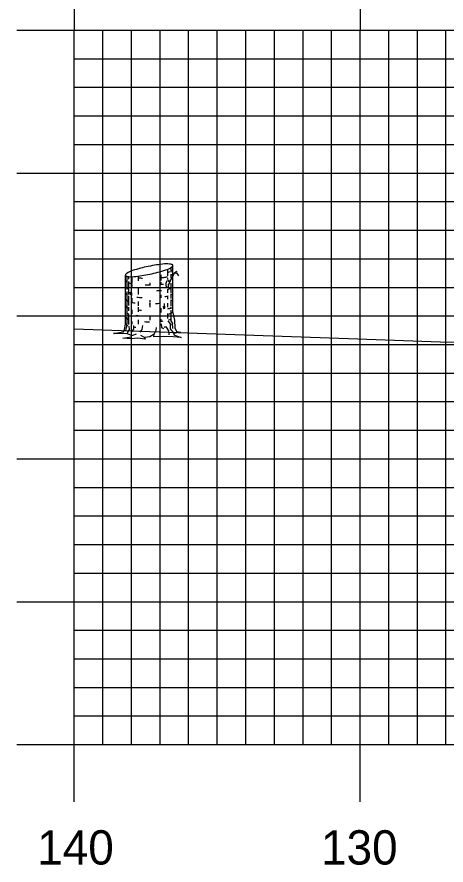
# Model space of a CAD drawing. Extents: x 1771235 to 1771579, y 442591 to 442811.
# Drawn here: x 1771259.06 to 1771274.07, y 442649.45 to 442679.13 of the extents above; entities that cross this region are included whole.
import ezdxf

# ---------------------------------------------------------------- set-up
doc = ezdxf.new("R2010")
doc.units = 0
for name, color, linetype in [('H_V ANNOTATION', 7, 'Continuous'), ('M_Trees_Conifer_Pay', 7, 'Continuous'), ('MAJOR', 7, 'Continuous'), ('MINOR', 7, 'Continuous'), ('S_Roadway_Centerline', 7, 'Continuous')]:
    doc.layers.add(name, color=color, linetype=linetype)

msp = doc.modelspace()

# ---------------------------------------------------------------- linework, layer by layer
at = {"layer": 'M_Trees_Conifer_Pay'}
for p, q in [((1771264.517, 442668.783), (1771264.517, 442670.429)), ((1771262.853, 442668.372), (1771262.853, 442670.094)), ((1771264.1, 442670.1), (1771264.1, 442669.901)), ((1771264.328, 442670.296), (1771264.328, 442670.073)), ((1771264.446, 442670.357), (1771264.446, 442670.195)), ((1771264.446, 442670.127), (1771264.446, 442669.999)), ((1771262.901, 442670.057), (1771262.901, 442669.586)), ((1771262.959, 442670.046), (1771262.959, 442669.948)), ((1771262.959, 442669.874), (1771262.959, 442669.67)), ((1771263.084, 442670.038), (1771263.084, 442669.805)), ((1771263.304, 442670.058), (1771263.304, 442669.89)), ((1771263.71, 442669.826), (1771263.71, 442669.731)), ((1771264.1, 442669.843), (1771264.1, 442669.754)), ((1771264.328, 442669.985), (1771264.328, 442669.937)), ((1771264.386, 442669.802), (1771264.334, 442669.742)), ((1771264.446, 442669.812), (1771264.446, 442669.476)), ((1771262.901, 442669.521), (1771262.901, 442669.213)), ((1771262.959, 442669.612), (1771262.959, 442669.412)), ((1771263.084, 442669.765), (1771263.084, 442669.691)), ((1771263.304, 442669.653), (1771263.304, 442669.416)), ((1771264.328, 442669.602), (1771264.328, 442669.47)), ((1771262.959, 442669.365), (1771262.959, 442669.029)), ((1771263.084, 442669.287), (1771263.084, 442669.149)), ((1771263.71, 442669.213), (1771263.71, 442669.139)), ((1771264.1, 442669.407), (1771264.1, 442669.302)), ((1771264.328, 442669.359), (1771264.328, 442669.25)), ((1771264.446, 442669.439), (1771264.446, 442669.277)), ((1771264.446, 442669.229), (1771264.446, 442669.013)), ((1771262.901, 442669.166), (1771262.901, 442668.674)), ((1771262.959, 442668.976), (1771262.959, 442668.84)), ((1771263.304, 442669.172), (1771263.304, 442669.019)), ((1771263.304, 442668.976), (1771263.304, 442668.803)), ((1771263.71, 442669.114), (1771263.71, 442668.966)), ((1771264.1, 442668.935), (1771264.1, 442668.788)), ((1771264.328, 442669.114), (1771264.328, 442668.972)), ((1771264.446, 442668.982), (1771264.446, 442668.908)), ((1771262.901, 442668.62), (1771262.901, 442668.372)), ((1771262.959, 442668.741), (1771262.959, 442668.363)), ((1771263.084, 442668.877), (1771263.084, 442668.735)), ((1771263.71, 442668.674), (1771263.71, 442668.521)), ((1771264.328, 442668.745), (1771264.328, 442668.573)), ((1771264.446, 442668.867), (1771264.446, 442668.694)), ((1771263.084, 442668.473), (1771263.084, 442668.379)), ((1771263.304, 442668.525), (1771263.304, 442668.372)), ((1771264.1, 442668.556), (1771264.1, 442668.468)), ((1771263.084, 442667.979), (1771263.247, 442668.043)), ((1771263.521, 442667.915), (1771263.395, 442667.979))]:
    msp.add_line(p, q, dxfattribs=at)
for points in [[(1771264.334, 442669.928), (1771264.371, 442669.853), (1771264.418, 442669.91), (1771264.476, 442669.979), (1771264.569, 442670.172), (1771264.633, 442670.22), (1771264.664, 442670.226)], [(1771264.349, 442669.674), (1771264.386, 442669.802), (1771264.449, 442669.917), (1771264.48, 442669.985), (1771264.549, 442670.131)], [(1771264.563, 442670.16), (1771264.639, 442670.168), (1771264.711, 442670.069)], [(1771264.301, 442669.89), (1771264.27, 442669.805), (1771264.266, 442669.738), (1771264.297, 442669.674)], [(1771263.033, 442669.4), (1771263.027, 442669.495), (1771263.07, 442669.472), (1771263.07, 442669.378)], [(1771264.172, 442669.001), (1771264.184, 442668.924), (1771264.231, 442668.935), (1771264.219, 442669.101)], [(1771264.517, 442668.783), (1771264.569, 442668.521), (1771264.585, 442668.247), (1771264.643, 442668.122), (1771264.779, 442668.091), (1771264.548, 442668.054), (1771264.548, 442668.054), (1771264.554, 442668.006), (1771264.802, 442667.912), (1771264.527, 442667.928), (1771264.172, 442667.949), (1771263.85, 442667.938), (1771263.857, 442668.021), (1771263.708, 442667.938), (1771263.521, 442667.915), (1771263.546, 442667.847), (1771263.278, 442667.891), (1771263.058, 442667.864), (1771262.765, 442667.881), (1771263.054, 442667.938), (1771263.084, 442667.979), (1771262.922, 442668.037), (1771262.685, 442668.048), (1771262.444, 442668.048), (1771262.786, 442668.105), (1771262.827, 442668.185), (1771262.853, 442668.372)], [(1771264.443, 442668.64), (1771264.449, 442668.494), (1771264.496, 442668.426), (1771264.507, 442668.227)], [(1771262.901, 442668.325), (1771262.88, 442668.247), (1771262.86, 442668.153)], [(1771262.979, 442668.305), (1771262.985, 442668.189), (1771262.932, 442668.101), (1771262.922, 442668.037)], [(1771263.142, 442668.332), (1771263.142, 442668.2), (1771263.054, 442668.101)], [(1771263.369, 442668.091), (1771263.436, 442668.185), (1771263.463, 442668.325)], [(1771264.107, 442668.389), (1771264.118, 442668.263), (1771264.192, 442668.22)], [(1771264.344, 442668.494), (1771264.418, 442668.389), (1771264.423, 442668.216), (1771264.548, 442668.054)], [(1771263.857, 442668.021), (1771263.931, 442668.162), (1771263.941, 442668.263)], [(1771264.386, 442668), (1771264.371, 442668.138), (1771264.297, 442668.267)]]:
    msp.add_lwpolyline(points, dxfattribs=at)
for centre, radius, start, end in [((1771264.709, 442665.327), 5.179, 101.7194, 108.0594), ((1771264.709, 442665.327), 5.179, 95.3794, 101.7194), ((1771264.299, 442669.685), 0.802, 79.2194, 95.3794), ((1771264.019, 442671.035), 0.802, 288.0594, 304.2194), ((1771264.402, 442670.226), 0.251, 71.0501, 79.2194), ((1771264.329, 442670.58), 0.251, 304.2194, 312.3887), ((1771264.457, 442670.386), 0.0817, 56.7194, 71.0501), ((1771264.442, 442670.455), 0.0817, 312.3887, 326.7194), ((1771264.473, 442670.41), 0.0527, 46.923, 56.7194), ((1771264.487, 442670.425), 0.0314, 34.2194, 46.923), ((1771264.467, 442670.439), 0.0527, 326.7194, 336.5158), ((1771264.491, 442670.428), 0.0264, 23.4074, 34.2194), ((1771264.486, 442670.431), 0.0314, 336.5158, 349.2194), ((1771264.495, 442670.43), 0.0226, 11.7194, 23.4074), ((1771264.495, 442670.43), 0.0226, 0.0315, 11.7194), ((1771264.491, 442670.43), 0.0264, 349.2194, 0.0315), ((1771262.885, 442670.093), 0.0314, 156.5158, 169.2194), ((1771262.88, 442670.094), 0.0264, 169.2194, 180.0315), ((1771262.876, 442670.094), 0.0226, 180.0315, 191.7194), ((1771262.876, 442670.094), 0.0226, 191.7194, 203.4074), ((1771262.88, 442670.095), 0.0264, 203.4074, 214.2194), ((1771262.904, 442670.084), 0.0527, 146.7194, 156.5158), ((1771262.884, 442670.098), 0.0314, 214.2194, 226.923), ((1771262.929, 442670.069), 0.0817, 132.3887, 146.7194), ((1771262.898, 442670.114), 0.0527, 226.923, 236.7194), ((1771262.914, 442670.138), 0.0817, 236.7194, 251.0501), ((1771263.042, 442669.944), 0.251, 124.2194, 132.3887), ((1771263.352, 442669.488), 0.802, 108.0594, 124.2194), ((1771262.662, 442675.197), 5.179, 275.3794, 281.7194), ((1771262.662, 442675.197), 5.179, 281.7194, 288.0594), ((1771264.187, 442670.743), 0.571, 284.4317, 292.4132), ((1771264.187, 442670.589), 0.571, 297.0237, 300), ((1771264.386, 442670.398), 0.172, 300, 311.2506), ((1771264.386, 442670.244), 0.172, 300, 311.2506), ((1771264.458, 442670.315), 0.0624, 311.2506, 330), ((1771264.458, 442670.161), 0.0624, 311.2506, 330), ((1771264.474, 442670.306), 0.0441, 330, 343.9485), ((1771264.474, 442670.152), 0.0441, 330, 343.9485), ((1771264.484, 442670.303), 0.0334, 343.9485, 354.2151), ((1771264.484, 442670.149), 0.0334, 343.9485, 354.2151), ((1771262.886, 442669.916), 0.0334, 163.9485, 180), ((1771262.886, 442669.916), 0.0334, 180, 196.0515), ((1771262.896, 442669.919), 0.0441, 196.0515, 210), ((1771262.912, 442669.928), 0.0624, 210, 228.7494), ((1771262.984, 442670.011), 0.172, 228.7494, 240), ((1771262.969, 442670.298), 0.251, 251.0501, 259.2194), ((1771263.183, 442670.356), 0.571, 240, 240.3367), ((1771263.072, 442670.839), 0.802, 259.2194, 275.3794), ((1771263.183, 442670.356), 0.571, 246.8597, 257.9846), ((1771263.686, 442674.106), 4.124, 264.6955, 266.7331), ((1771263.684, 442673.873), 4.124, 275.7849, 277.0558), ((1771263.686, 442674.106), 4.124, 276.238, 278.1032), ((1771264.187, 442670.589), 0.571, 278.1032, 284.3667), ((1771262.886, 442669.469), 0.0334, 163.9485, 180), ((1771263.185, 442670.145), 0.571, 240, 247.0587), ((1771263.684, 442673.873), 4.124, 268.0751, 270), ((1771263.684, 442673.873), 4.124, 270, 270.3581), ((1771263.686, 442673.662), 4.124, 273.7052, 275.9504), ((1771264.186, 442670.145), 0.571, 284.4493, 297.0429), ((1771264.484, 442669.705), 0.0334, 343.9485, 354.2151), ((1771262.886, 442669.469), 0.0334, 180, 196.0515), ((1771262.886, 442669.259), 0.0334, 163.9485, 180), ((1771262.886, 442669.259), 0.0334, 180, 196.0515), ((1771262.896, 442669.472), 0.0441, 196.0515, 210), ((1771262.896, 442669.262), 0.0441, 196.0515, 210), ((1771262.912, 442669.481), 0.0624, 210, 228.7494), ((1771262.912, 442669.271), 0.0624, 210, 228.7494), ((1771262.984, 442669.564), 0.172, 228.7494, 240), ((1771262.984, 442669.354), 0.172, 228.7494, 240), ((1771263.183, 442669.909), 0.571, 240, 240.3367), ((1771263.183, 442669.699), 0.571, 240, 246.8597), ((1771263.684, 442673.426), 4.124, 264.081, 266.6676), ((1771263.684, 442673.426), 4.124, 277.6125, 278.1032), ((1771264.185, 442669.909), 0.571, 278.1032, 286.9296), ((1771264.185, 442669.909), 0.571, 297.1896, 300), ((1771264.185, 442669.699), 0.571, 297.1896, 300), ((1771264.384, 442669.564), 0.172, 300, 311.2506), ((1771264.384, 442669.354), 0.172, 300, 311.2506), ((1771264.457, 442669.481), 0.0624, 311.2506, 330), ((1771264.457, 442669.271), 0.0624, 311.2506, 330), ((1771264.473, 442669.472), 0.0441, 330, 343.9485), ((1771264.473, 442669.262), 0.0441, 330, 343.9485), ((1771264.483, 442669.469), 0.0334, 343.9485, 354.2151), ((1771264.483, 442669.259), 0.0334, 343.9485, 354.2151), ((1771262.886, 442669.022), 0.0334, 163.9485, 180), ((1771262.886, 442669.022), 0.0334, 180, 196.0515), ((1771262.896, 442669.025), 0.0441, 196.0515, 210), ((1771262.912, 442669.034), 0.0624, 210, 228.7494), ((1771262.984, 442669.117), 0.172, 228.7494, 240), ((1771263.183, 442669.462), 0.571, 240, 246.8597), ((1771263.183, 442669.699), 0.571, 259.2707, 261.8968), ((1771263.684, 442673.216), 4.124, 261.8968, 263.1474), ((1771263.684, 442673.216), 4.124, 270, 270.3581), ((1771263.684, 442673.216), 4.124, 273.1493, 275.4569), ((1771264.185, 442669.462), 0.571, 285.3983, 297.1896), ((1771262.886, 442668.825), 0.0334, 163.9485, 180), ((1771262.886, 442668.629), 0.0334, 163.9485, 180), ((1771262.886, 442668.629), 0.0334, 180, 196.0515), ((1771262.896, 442668.632), 0.0441, 196.0515, 210), ((1771262.912, 442668.641), 0.0624, 210, 228.7494), ((1771262.984, 442668.724), 0.172, 228.7494, 240), ((1771263.173, 442669.271), 0.571, 241.2369, 248.0268), ((1771263.684, 442672.782), 4.124, 263.4991, 265.8397), ((1771263.684, 442672.98), 4.124, 264.716, 266.3193), ((1771264.185, 442669.264), 0.571, 289.2907, 300), ((1771264.384, 442668.919), 0.172, 300, 311.2506), ((1771264.457, 442668.837), 0.0624, 311.2506, 330), ((1771264.473, 442668.828), 0.0441, 330, 343.9485), ((1771264.483, 442668.825), 0.0334, 343.9485, 354.2151), ((1771262.886, 442668.409), 0.0334, 163.9485, 180), ((1771262.886, 442668.409), 0.0334, 180, 196.0515), ((1771262.896, 442668.412), 0.0441, 196.0515, 210), ((1771262.912, 442668.421), 0.0624, 210, 228.7494), ((1771262.984, 442668.503), 0.172, 228.7494, 240), ((1771263.183, 442669.069), 0.571, 240, 246.8597), ((1771263.183, 442668.849), 0.571, 240, 244.5314), ((1771263.684, 442672.586), 4.124, 267.8117, 270), ((1771263.684, 442672.586), 4.124, 270, 270.1328), ((1771263.684, 442672.586), 4.124, 275.7849, 276.7896), ((1771264.185, 442668.849), 0.571, 278.1032, 281.637), ((1771264.185, 442669.069), 0.571, 288.5067, 297.2721), ((1771264.384, 442668.503), 0.172, 300, 311.2506), ((1771264.457, 442668.421), 0.0624, 311.2506, 330), ((1771264.473, 442668.412), 0.0441, 330, 343.9485), ((1771264.483, 442668.409), 0.0334, 343.9485, 354.2151), ((1771263.684, 442672.366), 4.124, 262.4438, 263.512), ((1771263.684, 442672.366), 4.124, 277.3684, 278.1032)]:
    msp.add_arc(centre, radius, start, end, dxfattribs=at)
at = {"layer": 'MAJOR'}
for p, q in [((1771261.067, 442680.669), (1771261.067, 442678.665)), ((1771271.067, 442680.669), (1771271.067, 442678.665)), ((1771259.063, 442678.665), (1771261.067, 442678.665)), ((1771261.067, 442678.665), (1771541.067, 442678.665)), ((1771261.067, 442653.665), (1771261.067, 442678.665)), ((1771261.067, 442653.665), (1771261.067, 442678.665)), ((1771261.067, 442678.665), (1771541.067, 442678.665)), ((1771271.067, 442653.665), (1771271.067, 442678.665)), ((1771259.063, 442673.665), (1771261.067, 442673.665)), ((1771261.067, 442673.665), (1771541.067, 442673.665)), ((1771259.063, 442668.665), (1771261.067, 442668.665)), ((1771261.067, 442668.665), (1771541.067, 442668.665)), ((1771259.063, 442663.665), (1771261.067, 442663.665)), ((1771261.067, 442663.665), (1771541.067, 442663.665)), ((1771259.063, 442658.665), (1771261.067, 442658.665)), ((1771261.067, 442658.665), (1771541.067, 442658.665)), ((1771259.063, 442653.665), (1771261.067, 442653.665)), ((1771261.067, 442653.665), (1771541.067, 442653.665)), ((1771261.067, 442653.665), (1771541.067, 442653.665)), ((1771261.067, 442651.661), (1771261.067, 442653.665)), ((1771271.067, 442651.661), (1771271.067, 442653.665))]:
    msp.add_line(p, q, dxfattribs=at)
at = {"layer": 'MINOR'}
for p, q in [((1771262.067, 442653.665), (1771262.067, 442678.665)), ((1771263.067, 442653.665), (1771263.067, 442678.665)), ((1771264.067, 442653.665), (1771264.067, 442678.665)), ((1771265.067, 442653.665), (1771265.067, 442678.665)), ((1771266.067, 442653.665), (1771266.067, 442678.665)), ((1771267.067, 442653.665), (1771267.067, 442678.665)), ((1771268.067, 442653.665), (1771268.067, 442678.665)), ((1771269.067, 442653.665), (1771269.067, 442678.665)), ((1771270.067, 442653.665), (1771270.067, 442678.665)), ((1771272.067, 442653.665), (1771272.067, 442678.665)), ((1771273.067, 442653.665), (1771273.067, 442678.665)), ((1771274.067, 442653.665), (1771274.067, 442678.665)), ((1771261.067, 442677.665), (1771541.067, 442677.665)), ((1771261.067, 442677.665), (1771263.071, 442677.665)), ((1771261.067, 442676.665), (1771541.067, 442676.665)), ((1771261.067, 442676.665), (1771263.071, 442676.665)), ((1771261.067, 442675.665), (1771541.067, 442675.665)), ((1771261.067, 442675.665), (1771263.071, 442675.665)), ((1771261.067, 442674.665), (1771541.067, 442674.665)), ((1771261.067, 442674.665), (1771263.071, 442674.665)), ((1771261.067, 442672.665), (1771541.067, 442672.665)), ((1771261.067, 442672.665), (1771263.071, 442672.665)), ((1771261.067, 442671.665), (1771541.067, 442671.665)), ((1771261.067, 442671.665), (1771263.071, 442671.665)), ((1771261.067, 442670.665), (1771541.067, 442670.665)), ((1771261.067, 442670.665), (1771263.071, 442670.665)), ((1771261.067, 442669.665), (1771541.067, 442669.665)), ((1771261.067, 442669.665), (1771263.071, 442669.665)), ((1771261.067, 442667.665), (1771541.067, 442667.665)), ((1771261.067, 442667.665), (1771263.071, 442667.665)), ((1771261.067, 442666.665), (1771541.067, 442666.665)), ((1771261.067, 442666.665), (1771263.071, 442666.665)), ((1771261.067, 442665.665), (1771541.067, 442665.665)), ((1771261.067, 442665.665), (1771263.071, 442665.665)), ((1771261.067, 442664.665), (1771541.067, 442664.665)), ((1771261.067, 442664.665), (1771263.071, 442664.665)), ((1771261.067, 442662.665), (1771541.067, 442662.665)), ((1771261.067, 442662.665), (1771263.071, 442662.665)), ((1771261.067, 442661.665), (1771541.067, 442661.665)), ((1771261.067, 442661.665), (1771263.071, 442661.665)), ((1771261.067, 442660.665), (1771541.067, 442660.665)), ((1771261.067, 442660.665), (1771263.071, 442660.665)), ((1771261.067, 442659.665), (1771541.067, 442659.665)), ((1771261.067, 442659.665), (1771263.071, 442659.665)), ((1771261.067, 442657.665), (1771541.067, 442657.665)), ((1771261.067, 442657.665), (1771263.071, 442657.665)), ((1771261.067, 442656.665), (1771541.067, 442656.665)), ((1771261.067, 442656.665), (1771263.071, 442656.665)), ((1771261.067, 442655.665), (1771541.067, 442655.665)), ((1771261.067, 442655.665), (1771263.071, 442655.665)), ((1771261.067, 442654.665), (1771541.067, 442654.665)), ((1771261.067, 442654.665), (1771263.071, 442654.665))]:
    msp.add_line(p, q, dxfattribs=at)
at = {"layer": 'S_Roadway_Centerline'}
msp.add_lwpolyline([(1771261.067, 442668.217), (1771270.986, 442667.868), (1771273.863, 442667.761), (1771278.882, 442667.689), (1771292.748, 442667.403), (1771296.027, 442667.372), (1771313.506, 442667.004), (1771319.254, 442666.854), (1771327.568, 442666.756), (1771333.743, 442666.634), (1771343.154, 442666.376), (1771353.348, 442666.07)], dxfattribs=at)

# ---------------------------------------------------------------- texts
at = {"layer": 'H_V ANNOTATION'}
for s, p in [('140', (1771259.772, 442649.465)), ('130', (1771269.697, 442649.465))]:
    msp.add_text(s, height=1.2, dxfattribs=at).set_placement(p)
at = {"layer": 'MAJOR'}
msp.add_text('-', height=0.012, dxfattribs=at).set_placement((1771261.058, 442653.665))

doc.saveas('drawing.dxf')
